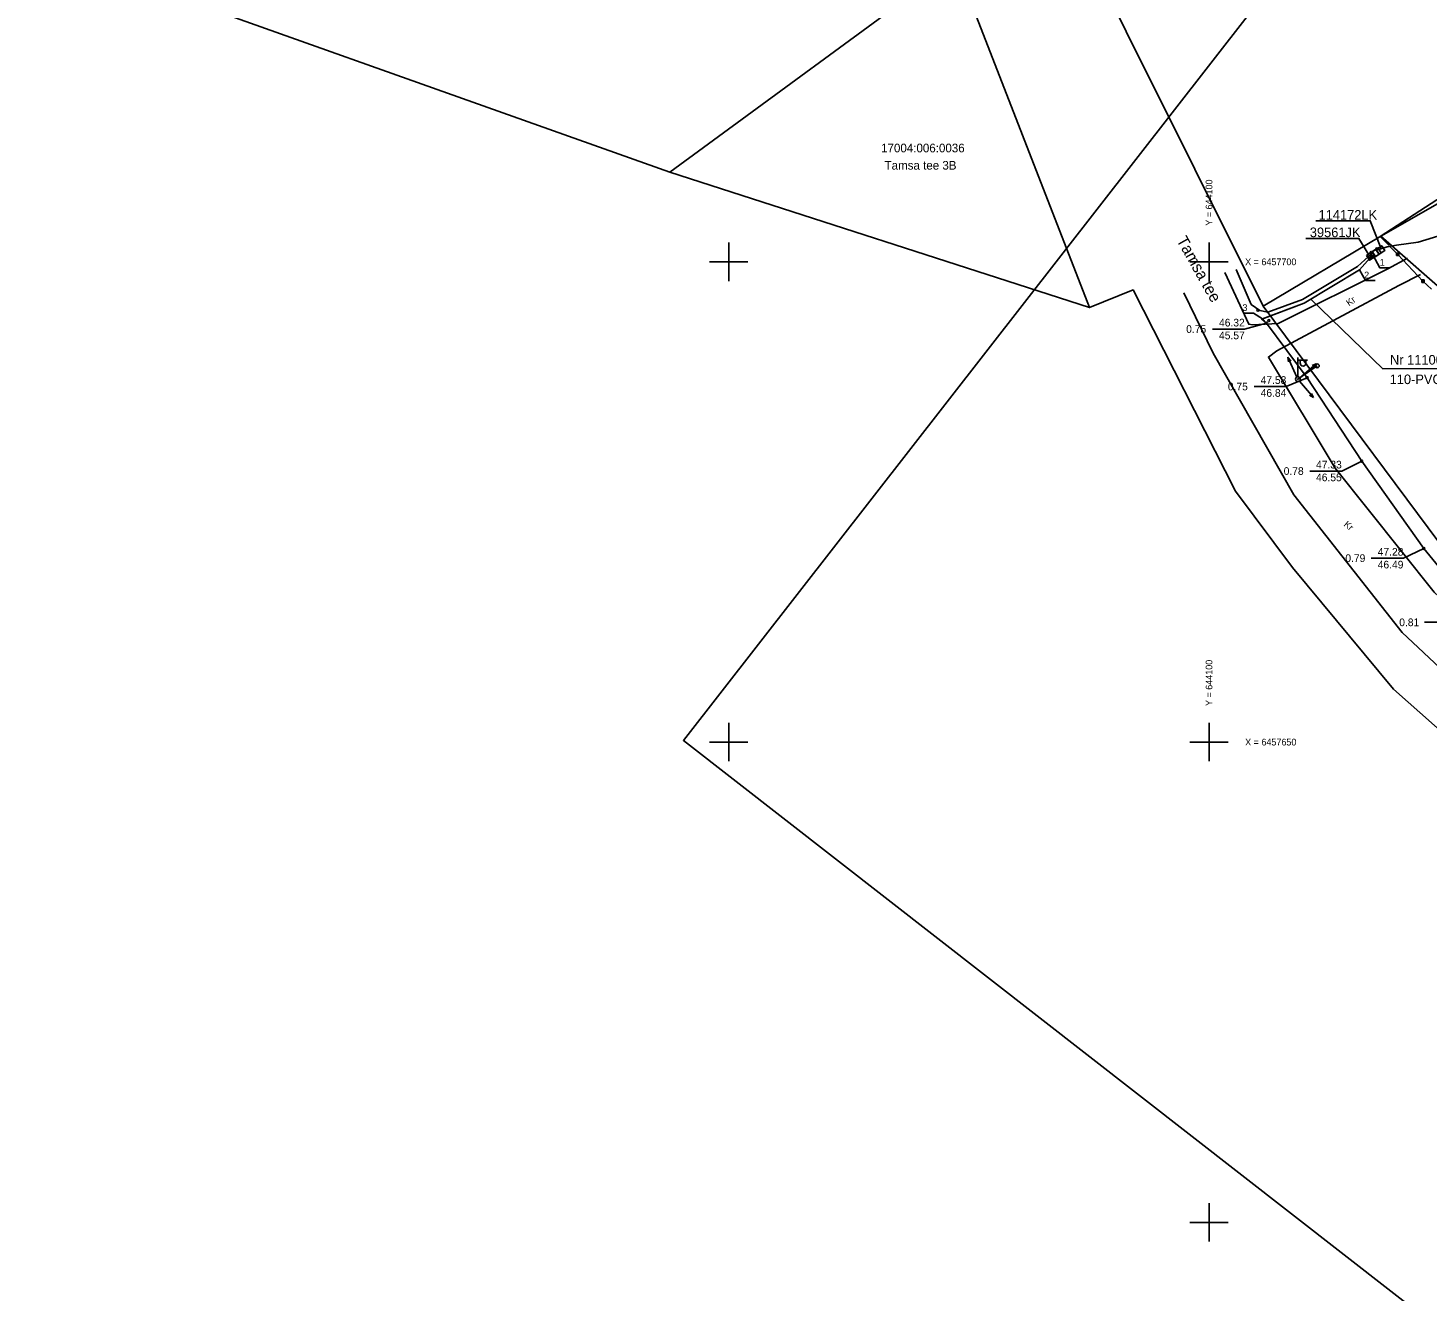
# Model space of a CAD drawing. Extents: x 643977 to 644381, y 6457457 to 6457867.
# Drawn here: x 643977.1 to 644122.8, y 6457592.9 to 6457724.3 of the extents above; entities that cross this region are included whole.
import ezdxf

# ---------------------------------------------------------------- set-up
doc = ezdxf.new("R2010")
doc.units = 0
for name, color, linetype in [('004 MPP EE @ 1 (1)', 7, 'Continuous'), ('005 MPO EE @ 1 (1)', 7, 'Continuous'), ('005 MPO EE @ 1 (2)', 7, 'Continuous'), ('007 PIIR EE', 7, 'Continuous'), ('007 PIIR1 EE', 7, 'Continuous'), ('MOOTMPUNKT', 7, 'Continuous'), ('TEE', 7, 'Continuous'), ('UUS', 7, 'Continuous'), ('VORK', 7, 'Continuous'), ('VORMISTUS', 7, 'Continuous')]:
    doc.layers.add(name, color=color, linetype=linetype)

msp = doc.modelspace()

# ---------------------------------------------------------------- linework, layer by layer
at = {"layer": '004 MPP EE @ 1 (1)'}
for p, q in [((644119.52, 6457700.9), (644119.52, 6457700.65)), ((644119.52, 6457700.9), (644119.77, 6457700.9)), ((644119.77, 6457700.9), (644119.77, 6457700.65)), ((644119.52, 6457700.65), (644119.77, 6457700.65)), ((644122.15, 6457698.11), (644122.15, 6457697.86)), ((644122.15, 6457698.11), (644122.4, 6457698.11)), ((644122.15, 6457697.86), (644122.4, 6457697.86)), ((644122.4, 6457698.11), (644122.4, 6457697.86))]:
    msp.add_line(p, q, dxfattribs=at)
msp.add_lwpolyline([(644130.68, 6457710.97), (644117.82, 6457702.64), (644119.64, 6457700.77), (644122.27, 6457697.99), (644123.17, 6457697.16)], dxfattribs=at)
at = {"layer": '005 MPO EE @ 1 (1)'}
for p, q in [((644116.77, 6457700.91), (644117.09, 6457700.41)), ((644116.99, 6457701.06), (644117.32, 6457700.56)), ((644117.37, 6457701.28), (644117.7, 6457700.78)), ((644117.6, 6457701.43), (644117.92, 6457700.93)), ((644109.25, 6457688.03), (644109.25, 6457690.03)), ((644109.25, 6457689.78), (644110.25, 6457689.78)), ((644111.27, 6457689.17), (644109.25, 6457687.78)), ((644109.48, 6457689.46), (644109.48, 6457689.78)), ((644110.09, 6457689.46), (644110.09, 6457689.78))]:
    msp.add_line(p, q, dxfattribs=at)
for points in [[(644111.12, 6457704.28), (644116.79, 6457704.28), (644117.88, 6457701.46)], [(644116.64, 6457700.73), (644115.6, 6457702.44), (644110.08, 6457702.44)]]:
    msp.add_lwpolyline(points, dxfattribs=at)
for points in [[(644116.38, 6457700.66), (644117.38, 6457701.31), (644117.71, 6457700.81), (644116.71, 6457700.16)], [(644116.98, 6457701.03), (644117.98, 6457701.68), (644118.31, 6457701.18), (644117.31, 6457700.53)]]:
    msp.add_lwpolyline(points, close=True, dxfattribs=at)
for centre, radius in [((644111.27, 6457689.17), 0.2), ((644109.25, 6457687.78), 0.25), ((644109.25, 6457687.78), 0.0234)]:
    msp.add_circle(centre, radius, dxfattribs=at)
msp.add_arc((644109.79, 6457689.46), 0.306, 180, 0, dxfattribs=at)
at = {"layer": '005 MPO EE @ 1 (2)'}
for points in [[(644120.67, 6457700.39), (644118.61, 6457699.27), (644107.2, 6457693.59), (644104.51, 6457693.44)], [(644104.51, 6457693.44), (644104.14, 6457693.5), (644101.64, 6457698.88)], [(644146.19, 6457645.77), (644136.9, 6457653.15), (644123.42, 6457665.62), (644113.13, 6457678.52), (644106.19, 6457690.08), (644107.06, 6457690.75), (644119.77, 6457697.52), (644122.01, 6457698.68)], [(644097.36, 6457696.77), (644100.44, 6457690.48), (644108.83, 6457675.73), (644120.12, 6457661.42), (644132.97, 6457649.32), (644147.71, 6457637.83), (644162.19, 6457626.8)]]:
    msp.add_lwpolyline(points, dxfattribs=at)
at = {"layer": '007 PIIR EE'}
for p, q in [((644108.22, 6457690.06), (644108.27, 6457689.58)), ((644108.22, 6457690.06), (644108.54, 6457689.71)), ((644109.15, 6457688.01), (644108.22, 6457690.06)), ((644109.45, 6457687.94), (644111.17, 6457689.38)), ((644111.17, 6457689.38), (644110.73, 6457689.21)), ((644111.17, 6457689.38), (644110.92, 6457688.98)), ((644109.41, 6457687.59), (644110.86, 6457685.86)), ((644110.86, 6457685.86), (644110.45, 6457686.11)), ((644110.86, 6457685.86), (644110.68, 6457686.3))]:
    msp.add_line(p, q, dxfattribs=at)
at = {"layer": '007 PIIR1 EE'}
for points in [[(644117.56, 6457701.26), (644118.53, 6457701.57), (644119.51, 6457701.72), (644121.77, 6457702.04), (644126.68, 6457703.53), (644132.24, 6457703.6), (644137.78, 6457703.72), (644141.28, 6457703.01), (644143.77, 6457703.42), (644146.25, 6457704.61), (644147.33, 6457704.32), (644148.9, 6457702.67)], [(644116.98, 6457700.9), (644115.46, 6457699.5), (644109.74, 6457696.08), (644106.12, 6457694.75), (644105.28, 6457694.93), (644104.37, 6457695.56), (644102.81, 6457699.21)], [(644170.75, 6457632.71), (644170.64, 6457632.25), (644170.59, 6457631.82), (644170.29, 6457631.6), (644170.08, 6457631.62), (644162.86, 6457636.99), (644154.53, 6457643.4), (644152.81, 6457644.9), (644145.85, 6457649.47), (644136.59, 6457656.84), (644127.81, 6457663.51), (644122.37, 6457670.16), (644115.89, 6457679.24), (644110.22, 6457687.94), (644105.98, 6457693.61), (644105.49, 6457694.03), (644109.92, 6457695.7), (644115.67, 6457699.15), (644117.04, 6457700.73)], [(644170.75, 6457632.71), (644170.64, 6457632.25), (644170.59, 6457631.82), (644170.29, 6457631.6), (644170.08, 6457631.62), (644162.86, 6457636.99), (644154.53, 6457643.4), (644152.81, 6457644.9), (644145.85, 6457649.47), (644136.59, 6457656.84), (644127.81, 6457663.51), (644122.37, 6457670.16), (644115.89, 6457679.24), (644110.22, 6457687.94), (644105.98, 6457693.61), (644105.57, 6457694.06), (644109.92, 6457695.7), (644115.67, 6457699.15), (644117.04, 6457700.73)], [(644148.31, 6457688.88), (644118.1, 6457688.86), (644110.61, 6457696.12)], [(644105.98, 6457693.61), (644103.7, 6457693), (644100.37, 6457693)], [(644110.22, 6457687.94), (644108.04, 6457687.02), (644104.71, 6457687.02)], [(644115.89, 6457679.24), (644113.81, 6457678.22), (644110.48, 6457678.22)], [(644122.37, 6457670.16), (644120.23, 6457669.15), (644116.89, 6457669.15)], [(644127.81, 6457663.51), (644125.76, 6457662.47), (644122.43, 6457662.47)]]:
    msp.add_lwpolyline(points, dxfattribs=at)
at = {"layer": 'MOOTMPUNKT'}
for centre in [(644116.88, 6457700.98), (644117.48, 6457701.36), (644116.66, 6457700.53), (644116.86, 6457700.52), (644105.08, 6457694.98), (644105.98, 6457693.61), (644106.23, 6457693.88), (644110.22, 6457687.94), (644115.89, 6457679.24), (644122.37, 6457670.16)]:
    msp.add_circle(centre, 0.1, dxfattribs=at)
at = {"layer": 'TEE'}
for points in [[(643989.66, 6457760.08), (643987.33, 6457763.78), (643977.05, 6457733.09), (644043.85, 6457709.33), (644073.59, 6457731.16), (644069.76, 6457744.43), (644054.5, 6457738.54), (644041.41, 6457742.89)], [(644084.27, 6457738.29), (644105.62, 6457695.4), (644117.87, 6457702.68), (644141.47, 6457716.14), (644166.4, 6457723.98), (644161.44, 6457753.91), (644160.79, 6457756.77), (644152.83, 6457754.95), (644133.56, 6457751.83), (644087.35, 6457749.32), (644082.35, 6457742.69)], [(644073.59, 6457731.16), (644043.85, 6457709.33), (644087.56, 6457695.23)], [(644141.47, 6457716.14), (644117.87, 6457702.68), (644155.89, 6457669.35), (644185.98, 6457698.94), (644166.4, 6457723.98)]]:
    msp.add_lwpolyline(points, close=True, dxfattribs=at)
for points in [[(644128.57, 6457664.58), (644105.62, 6457695.4), (644084.27, 6457738.29)], [(644073.59, 6457731.16), (644087.56, 6457695.23), (644092.09, 6457697.08), (644102.74, 6457676.12), (644108.68, 6457668.18), (644119.21, 6457655.5), (644137.18, 6457639.57)]]:
    msp.add_lwpolyline(points, dxfattribs=at)
at = {"layer": 'UUS'}
for points in [[(644117.04, 6457700.73), (644117.77, 6457699.38), (644118.77, 6457699.38)], [(644115.67, 6457699.15), (644116.3, 6457698.05), (644117.3, 6457698.05)], [(644105.57, 6457694.06), (644104.63, 6457694.64), (644103.63, 6457694.64)]]:
    msp.add_lwpolyline(points, dxfattribs=at)
at = {"layer": 'VORK'}
for p, q in [((644050, 6457702), (644050, 6457698)), ((644100, 6457702), (644100, 6457698)), ((644048, 6457700), (644052, 6457700)), ((644098, 6457700), (644102, 6457700)), ((644050, 6457652), (644050, 6457648)), ((644100, 6457652), (644100, 6457648)), ((644048, 6457650), (644052, 6457650)), ((644098, 6457650), (644102, 6457650)), ((644100, 6457602), (644100, 6457598)), ((644098, 6457600), (644102, 6457600))]:
    msp.add_line(p, q, dxfattribs=at)
at = {"layer": 'VORMISTUS'}
msp.add_lwpolyline([(644374.21, 6457572.35), (644287.82, 6457461.37), (644045.28, 6457650.18), (644131.67, 6457761.15)], close=True, dxfattribs=at)

# ---------------------------------------------------------------- texts
at = {"layer": '005 MPO EE @ 1 (1)'}
for s, p in [('114172LK', (644111.4, 6457704.39)), ('39561JK', (644110.49, 6457702.57))]:
    msp.add_text(s, height=1, dxfattribs=at).set_placement(p)
at = {"layer": '005 MPO EE @ 1 (2)'}
for s, height, rotation, p in [('Tamsa tee', 1.2, 299.3244, (644096.58, 6457702.26)), ('Kr', 0.7, 35.7634, (644114.58, 6457695.35)), ('Kr', 0.7, 320.0006, (644113.96, 6457672.56))]:
    msp.add_text(s, height=height, rotation=rotation, dxfattribs=at).set_placement(p)
at = {"layer": '007 PIIR1 EE'}
for s, height, p in [('0.75', 0.8, (644097.62, 6457692.6)), ('46.32', 0.8, (644101.04, 6457693.27)), ('45.57', 0.8, (644101.04, 6457691.94)), ('Nr 11100 39561JK-40781JK AXPK4x120 L=105,9m', 1, (644118.84, 6457689.3)), ('47.58', 0.8, (644105.37, 6457687.29)), ('110-PVC kaitsetoru L=105,9m', 1, (644118.8, 6457687.27)), ('0.75', 0.8, (644101.96, 6457686.62)), ('46.84', 0.8, (644105.37, 6457685.95)), ('47.33', 0.8, (644111.14, 6457678.49)), ('0.78', 0.8, (644107.77, 6457677.82)), ('46.55', 0.8, (644111.14, 6457677.16)), ('47.28', 0.8, (644117.56, 6457669.41)), ('0.79', 0.8, (644114.19, 6457668.75)), ('46.49', 0.8, (644117.56, 6457668.08)), ('0.81', 0.8, (644119.8, 6457662.07))]:
    msp.add_text(s, height=height, dxfattribs=at).set_placement(p)
at = {"layer": 'TEE'}
for s, p in [('17004:006:0036', (644065.86, 6457711.4)), ('Tamsa tee 3B', (644066.22, 6457709.6))]:
    msp.add_text(s, height=0.9, dxfattribs=at).set_placement(p)
at = {"layer": 'UUS'}
for s, p in [(' 1', (644117.5, 6457699.59)), (' 2', (644115.89, 6457698.27)), (' 3', (644103.22, 6457694.88))]:
    msp.add_text(s, height=0.7, dxfattribs=at).set_placement(p)
at = {"layer": 'VORK'}
for p in [(644100.35, 6457703.5), (644100.35, 6457653.5)]:
    msp.add_text(' Y = 644100', height=0.7, rotation=90, dxfattribs=at).set_placement(p)
for s, p in [(' X = 6457700', (644103.5, 6457699.65)), (' X = 6457650', (644103.5, 6457649.65))]:
    msp.add_text(s, height=0.7, dxfattribs=at).set_placement(p)

doc.saveas('drawing.dxf')
